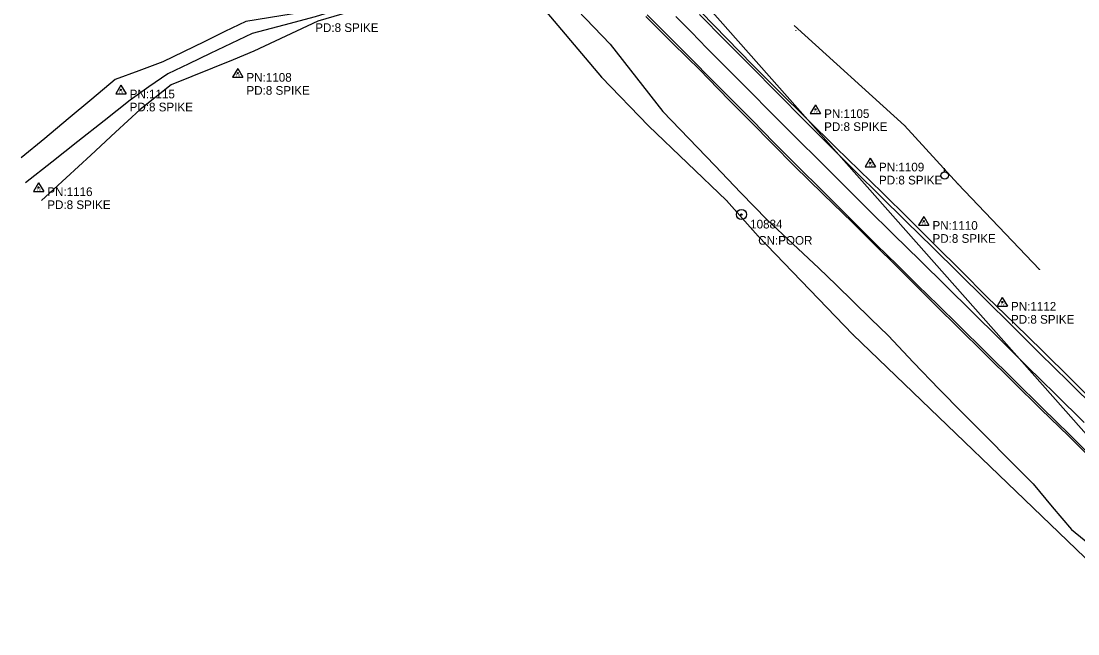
# Model space of a CAD drawing. Extents: x 592653 to 596268, y 1744647 to 1746025.
# Drawn here: x 593860 to 594468, y 1745163 to 1745516 of the extents above; entities that cross this region are included whole.
import ezdxf

# ---------------------------------------------------------------- set-up
doc = ezdxf.new("R2010")
doc.units = 0
for name, color, linetype in [('Default', 7, 'Continuous'), ('S_DITCHLINE', 7, 'Continuous'), ('S_EDGE_PAVEMENT', 7, 'Continuous'), ('S_FENCE', 7, 'Continuous'), ('S_FENCE_ANNOT', 7, 'Continuous'), ('S_IRON_PIN', 7, 'Continuous'), ('S_IRON_PIN_ANNOT', 7, 'Continuous'), ('S_MSC_PT_SYM', 7, 'Continuous'), ('S_PAVEMENT_CROWN', 7, 'Continuous'), ('S_SECONDARY_CTL', 7, 'Continuous'), ('S_SECONDARY_CTL_ANNOT', 7, 'Continuous'), ('S_SHOULDER', 7, 'Continuous'), ('S_STREAM', 7, 'Continuous'), ('S_UTILITY_POLE', 7, 'Continuous')]:
    doc.layers.add(name, color=color, linetype=linetype)

msp = doc.modelspace()

# ---------------------------------------------------------------- linework, layer by layer
at = {"layer": 'Default'}
msp.add_line((594217.16, 1745566.75), (594574.34, 1745162.93), dxfattribs=at)
at = {"layer": 'S_DITCHLINE'}
for points in [[(594166.09, 1745554.32), (594156.58, 1745547.17), (594161.47, 1745541.73), (594170.83, 1745531.87), (594180.18, 1745522.02), (594189.53, 1745512.16), (594198.89, 1745502.3), (594214.02, 1745482.98), (594229.16, 1745463.65)], [(594229.16, 1745463.65), (594244.17, 1745448.06), (594259.18, 1745432.47), (594274.19, 1745416.87), (594289.2, 1745401.28)], [(594289.2, 1745401.28), (594304.07, 1745387.38), (594318.93, 1745373.48), (594328.92, 1745363.76), (594338.91, 1745354.04), (594348.9, 1745344.32), (594358.89, 1745334.6), (594373.51, 1745319.15), (594388.13, 1745303.71), (594401.66, 1745290.09), (594415.2, 1745276.47), (594428.73, 1745262.85), (594442.26, 1745249.23), (594453.28, 1745236.08), (594464.29, 1745222.94), (594476.84, 1745212.79)]]:
    msp.add_lwpolyline(points, dxfattribs=at)
at = {"layer": 'S_EDGE_PAVEMENT'}
for points in [[(594220.26, 1745519.25), (594229.18, 1745510.28), (594238.1, 1745501.32), (594247.02, 1745492.36), (594255.95, 1745483.4), (594268.35, 1745470.88), (594280.75, 1745458.36), (594293.15, 1745445.84), (594305.56, 1745433.33), (594322.2, 1745416.72), (594338.85, 1745400.11), (594352.24, 1745386.82), (594364.02, 1745375.26), (594375.79, 1745363.69), (594387.57, 1745352.12), (594399.35, 1745340.55), (594415.4, 1745324.63), (594431.44, 1745308.72), (594447.37, 1745293.07), (594463.29, 1745277.42), (594473.77, 1745267.2)], [(594250.34, 1745519.49), (594265.15, 1745504.51), (594279.96, 1745489.54), (594294.76, 1745474.56), (594311.09, 1745458.1), (594327.41, 1745441.65), (594340.63, 1745428.52), (594353.85, 1745415.39), (594369.2, 1745400.35), (594384.54, 1745385.31), (594399.5, 1745370.55), (594414.46, 1745355.79), (594430.29, 1745340.04), (594446.12, 1745324.3), (594462.64, 1745308.13), (594479.16, 1745291.97)]]:
    msp.add_lwpolyline(points, dxfattribs=at)
at = {"layer": 'S_FENCE'}
for p, q in [((594151.71, 1745533.43), (594193.9, 1745483.36)), ((594304.83, 1745513.13), (594368.3, 1745455.62)), ((594193.9, 1745483.36), (594221.04, 1745455.37)), ((594221.04, 1745455.37), (594265.87, 1745412.43)), ((594368.3, 1745455.62), (594398.88, 1745422.06)), ((594398.88, 1745422.06), (594445.89, 1745372.58)), ((594265.87, 1745412.43), (594284.09, 1745391.93)), ((594284.09, 1745391.93), (594338.53, 1745335.34)), ((594338.53, 1745335.34), (594483.05, 1745196.12))]:
    msp.add_line(p, q, dxfattribs=at)
at = {"layer": 'S_IRON_PIN'}
for radius in [2.91, 0.411, 0.262, 0.212, 0.145, 0.0822, 0.0581]:
    msp.add_circle((594274.47, 1745404.28), radius, dxfattribs=at)
at = {"layer": 'S_MSC_PT_SYM'}
for points in [[(594304.83, 1745513.13), (594304.83, 1745513.18), (594304.83, 1745513.13), (594304.78, 1745513.13), (594304.83, 1745513.13), (594304.83, 1745513.08), (594304.83, 1745513.13), (594304.88, 1745513.13)], [(594305.73, 1745510.31), (594305.73, 1745510.36), (594305.73, 1745510.31), (594305.68, 1745510.31), (594305.73, 1745510.31), (594305.73, 1745510.26), (594305.73, 1745510.31), (594305.78, 1745510.31)], [(594193.9, 1745483.36), (594193.9, 1745483.41), (594193.9, 1745483.36), (594193.85, 1745483.36), (594193.9, 1745483.36), (594193.9, 1745483.31), (594193.9, 1745483.36), (594193.95, 1745483.36)], [(594221.04, 1745455.37), (594221.04, 1745455.42), (594221.04, 1745455.37), (594220.99, 1745455.37), (594221.04, 1745455.37), (594221.04, 1745455.32), (594221.04, 1745455.37), (594221.09, 1745455.37)], [(594368.3, 1745455.62), (594368.3, 1745455.67), (594368.3, 1745455.62), (594368.25, 1745455.62), (594368.3, 1745455.62), (594368.3, 1745455.57), (594368.3, 1745455.62), (594368.35, 1745455.62)], [(594398.88, 1745422.06), (594398.88, 1745422.11), (594398.88, 1745422.06), (594398.83, 1745422.06), (594398.88, 1745422.06), (594398.88, 1745422.01), (594398.88, 1745422.06), (594398.93, 1745422.06)], [(594265.87, 1745412.43), (594265.87, 1745412.48), (594265.87, 1745412.43), (594265.82, 1745412.43), (594265.87, 1745412.43), (594265.87, 1745412.38), (594265.87, 1745412.43), (594265.92, 1745412.43)], [(594284.09, 1745391.93), (594284.09, 1745391.98), (594284.09, 1745391.93), (594284.04, 1745391.93), (594284.09, 1745391.93), (594284.09, 1745391.88), (594284.09, 1745391.93), (594284.14, 1745391.93)], [(594445.89, 1745372.58), (594445.89, 1745372.63), (594445.89, 1745372.58), (594445.84, 1745372.58), (594445.89, 1745372.58), (594445.89, 1745372.53), (594445.89, 1745372.58), (594445.94, 1745372.58)], [(594338.53, 1745335.34), (594338.53, 1745335.39), (594338.53, 1745335.34), (594338.48, 1745335.34), (594338.53, 1745335.34), (594338.53, 1745335.29), (594338.53, 1745335.34), (594338.58, 1745335.34)]]:
    msp.add_lwpolyline(points, dxfattribs=at)
at = {"layer": 'S_PAVEMENT_CROWN'}
msp.add_lwpolyline([(594236.73, 1745518.28), (594245.68, 1745509.19), (594254.63, 1745500.1), (594263.59, 1745491.01), (594278.08, 1745476.41), (594292.58, 1745461.81), (594306.12, 1745448.31), (594319.65, 1745434.82), (594333.18, 1745421.32), (594346.71, 1745407.83), (594361.97, 1745392.8), (594377.23, 1745377.77), (594392.16, 1745363.03), (594407.09, 1745348.28), (594422.82, 1745332.68), (594438.55, 1745317.08), (594455.12, 1745300.86), (594471.69, 1745284.63)], dxfattribs=at)
at = {"layer": 'S_SECONDARY_CTL'}
for p, q in [((593984.71, 1745488.34), (593981.7, 1745483.39)), ((593984.71, 1745488.34), (593987.66, 1745483.39)), ((593981.7, 1745483.39), (593987.66, 1745483.39)), ((593917.51, 1745478.77), (593914.5, 1745473.82)), ((593917.51, 1745478.77), (593920.46, 1745473.82)), ((593914.5, 1745473.82), (593920.46, 1745473.82)), ((594317.04, 1745467.48), (594314.03, 1745462.53)), ((594317.04, 1745467.48), (594319.98, 1745462.53)), ((594314.03, 1745462.53), (594319.98, 1745462.53)), ((594348.58, 1745436.72), (594345.57, 1745431.77)), ((594348.58, 1745436.72), (594351.53, 1745431.77)), ((594345.57, 1745431.77), (594351.53, 1745431.77)), ((593870.14, 1745422.54), (593867.13, 1745417.58)), ((593870.14, 1745422.54), (593873.09, 1745417.58)), ((593867.13, 1745417.58), (593873.09, 1745417.58)), ((594379.36, 1745403.12), (594376.35, 1745398.17)), ((594379.36, 1745403.12), (594382.31, 1745398.17)), ((594376.35, 1745398.17), (594382.31, 1745398.17)), ((594424.52, 1745356.58), (594421.51, 1745351.62)), ((594424.52, 1745356.58), (594427.46, 1745351.62)), ((594421.51, 1745351.62), (594427.46, 1745351.62))]:
    msp.add_line(p, q, dxfattribs=at)
for centre, radius in [((593984.71, 1745485.73), 0.311), ((593984.71, 1745485.73), 0.183), ((593984.71, 1745485.73), 0.103), ((593917.51, 1745476.16), 0.311), ((593917.51, 1745476.16), 0.183), ((593917.51, 1745476.16), 0.103), ((594317.04, 1745464.87), 0.311), ((594317.04, 1745464.87), 0.183), ((594317.04, 1745464.87), 0.103), ((594348.58, 1745434.11), 0.311), ((594348.58, 1745434.11), 0.183), ((594348.58, 1745434.11), 0.103), ((593870.14, 1745419.93), 0.311), ((593870.14, 1745419.93), 0.183), ((593870.14, 1745419.93), 0.103), ((594379.36, 1745400.51), 0.311), ((594379.36, 1745400.51), 0.183), ((594379.36, 1745400.51), 0.103), ((594424.52, 1745353.97), 0.311), ((594424.52, 1745353.97), 0.183), ((594424.52, 1745353.97), 0.103)]:
    msp.add_circle(centre, radius, dxfattribs=at)
at = {"layer": 'S_SHOULDER'}
for points in [[(594251.28, 1745520.68), (594266.09, 1745505.59), (594280.9, 1745490.51), (594295.72, 1745475.42), (594312.26, 1745459.12), (594328.8, 1745442.82), (594342.17, 1745429.82), (594355.54, 1745416.83), (594370.76, 1745401.75), (594385.98, 1745386.68), (594400.81, 1745371.8), (594415.64, 1745356.92), (594431.69, 1745341.38), (594447.73, 1745325.84), (594464.18, 1745309.58), (594480.63, 1745293.32)], [(594219.37, 1745518.2), (594235.05, 1745502.77), (594250.73, 1745487.34), (594255.23, 1745482.56), (594267.6, 1745470.02), (594279.98, 1745457.48), (594292.35, 1745444.94), (594304.72, 1745432.41), (594321.5, 1745416.07), (594338.28, 1745399.74), (594351.62, 1745386.41), (594363.39, 1745374.74), (594375.17, 1745363.07), (594386.95, 1745351.4), (594398.72, 1745339.74), (594414.73, 1745323.89), (594430.74, 1745308.05), (594446.74, 1745292.36), (594462.74, 1745276.67), (594473.17, 1745266.44)]]:
    msp.add_lwpolyline(points, dxfattribs=at)
at = {"layer": 'S_STREAM'}
for points in [[(594121.51, 1745578.81), (594116.8, 1745556.87), (594105.51, 1745548.63), (594086.68, 1745539.13), (594072.4, 1745534.84), (594058.11, 1745530.56), (594043.83, 1745526.27), (594029.55, 1745521.98), (594009.42, 1745518.69), (593989.29, 1745515.39), (593977.35, 1745509.59), (593965.4, 1745503.78), (593953.45, 1745497.98), (593941.51, 1745492.18), (593927.89, 1745487.08), (593914.27, 1745481.98), (593900.72, 1745470.7), (593887.18, 1745459.42), (593873.64, 1745448.14), (593860.09, 1745436.87)], [(594137.06, 1745562.92), (594124.31, 1745556.22), (594111.56, 1745549.51), (594098.82, 1745542.81), (594086.07, 1745536.1), (594071.86, 1745531.58), (594057.65, 1745527.06), (594043.43, 1745522.54), (594029.22, 1745518.02), (594011.13, 1745513.25), (593993.03, 1745508.47), (593980.89, 1745502.69), (593968.75, 1745496.9), (593956.6, 1745491.11), (593944.46, 1745485.33), (593933.64, 1745477.75), (593922.83, 1745470.16), (593907.77, 1745458.25), (593892.71, 1745446.34), (593877.66, 1745434.43), (593862.6, 1745422.52)], [(594146.88, 1745558.89), (594130.58, 1745551.98), (594126.65, 1745549.15), (594111.68, 1745534.37), (594098.81, 1745533.18), (594085.94, 1745531.99), (594072.15, 1745527.89), (594058.36, 1745523.78), (594044.57, 1745519.68), (594030.78, 1745515.57), (594012.34, 1745506.91), (593993.89, 1745498.25), (593982.01, 1745493.42), (593970.13, 1745488.59), (593958.26, 1745483.76), (593946.38, 1745478.93), (593928.65, 1745464.69), (593914.46, 1745451.61), (593900.27, 1745438.53), (593886.09, 1745425.45), (593871.9, 1745412.37)]]:
    msp.add_lwpolyline(points, dxfattribs=at)
at = {"layer": 'S_UTILITY_POLE'}
msp.add_line((594391.24, 1745428.88), (594391.24, 1745430.99), dxfattribs=at)
msp.add_circle((594391.37, 1745426.74), 2.13, dxfattribs=at)

# ---------------------------------------------------------------- texts
at = {"layer": 'S_FENCE_ANNOT'}
msp.add_text('CN:POOR', height=5, dxfattribs=at).set_placement((594284.09, 1745386.93))
at = {"layer": 'S_IRON_PIN_ANNOT'}
msp.add_text('10884', height=5, dxfattribs=at).set_placement((594279.47, 1745396.28))
at = {"layer": 'S_SECONDARY_CTL'}
for p in [(593983.51, 1745483.72), (593916.31, 1745474.15), (594315.83, 1745462.86), (594347.38, 1745432.1), (593868.94, 1745417.92), (594378.16, 1745398.5), (594423.31, 1745351.95)]:
    msp.add_text('TV', height=1.5, rotation=360, dxfattribs=at).set_placement(p)
at = {"layer": 'S_SECONDARY_CTL_ANNOT'}
for s, p in [('PD:8 SPIKE', (594029.28, 1745509.37)), ('PN:1108', (593989.71, 1745480.73)), ('PN:1115', (593922.51, 1745471.16)), ('PD:8 SPIKE', (593989.71, 1745473.23)), ('PD:8 SPIKE', (593922.51, 1745463.66)), ('PN:1105', (594322.04, 1745459.87)), ('PD:8 SPIKE', (594322.04, 1745452.37)), ('PN:1109', (594353.58, 1745429.11)), ('PD:8 SPIKE', (594353.58, 1745421.61)), ('PN:1116', (593875.14, 1745414.93)), ('PD:8 SPIKE', (593875.14, 1745407.43)), ('PN:1110', (594384.36, 1745395.51)), ('PD:8 SPIKE', (594384.36, 1745388.01)), ('PN:1112', (594429.52, 1745348.97)), ('PD:8 SPIKE', (594429.52, 1745341.47))]:
    msp.add_text(s, height=5, dxfattribs=at).set_placement(p)

doc.saveas('drawing.dxf')
